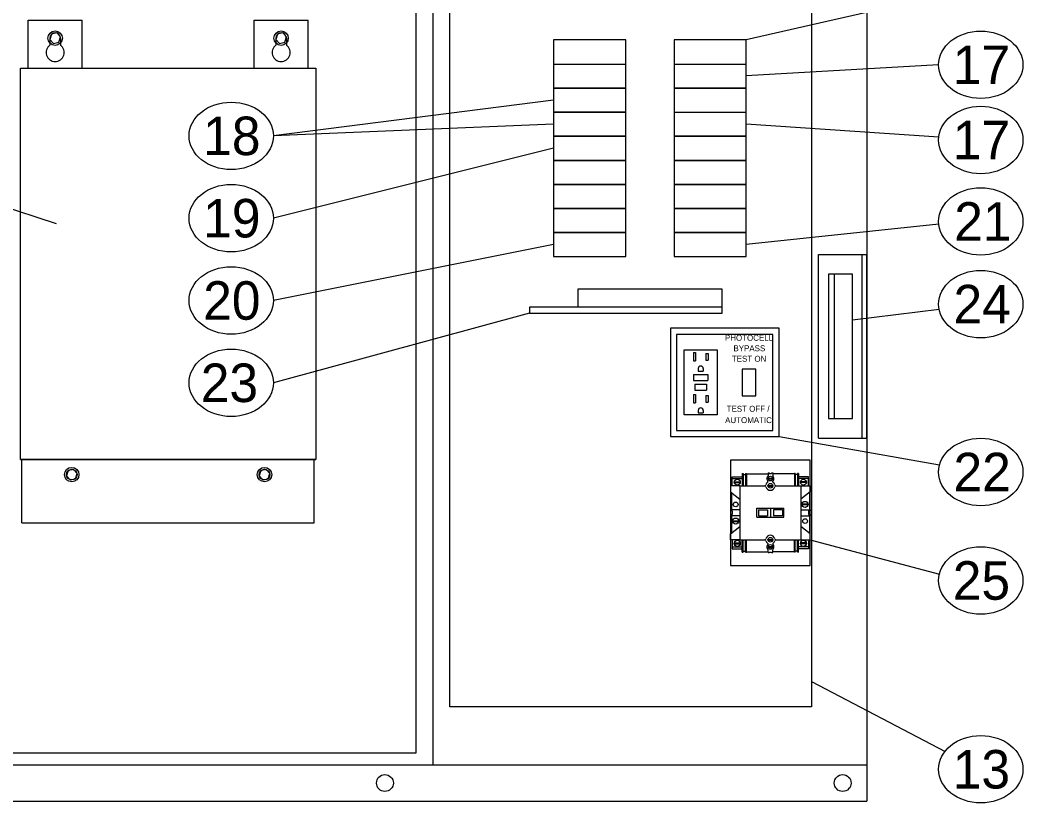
# Model space of a CAD drawing. Extents: x 99862 to 103680, y 99470 to 105076.
# Drawn here: x 102025.2 to 102441.5, y 104497.2 to 104822.4 of the extents above; entities that cross this region are included whole.
import ezdxf

# ---------------------------------------------------------------- set-up
doc = ezdxf.new("R2010")
doc.units = 0
for name, color, linetype in [('Level 1', 7, 'Continuous'), ('Level 15', 7, 'Continuous'), ('Level 20', 7, 'Continuous'), ('Level 40', 7, 'Continuous')]:
    doc.layers.add(name, color=color, linetype=linetype)

msp = doc.modelspace()

# ---------------------------------------------------------------- linework, layer by layer
at = {"layer": 'Level 1'}
for p, q in [((102203.66, 104537.04), (102203.66, 104897.04)), ((102353.66, 104897.04), (102353.66, 104537.04)), ((102189.66, 104518.01), (102189.66, 104892.87)), ((102028.51, 104802.34), (102028.51, 104822.34)), ((102028.51, 104822.34), (102051.01, 104822.34)), ((102051.01, 104802.34), (102051.01, 104822.34)), ((102122.31, 104802.34), (102122.31, 104822.34)), ((102122.31, 104822.34), (102144.81, 104822.34)), ((102144.81, 104802.34), (102144.81, 104822.34)), ((102037.56, 104814.84), (102037.56, 104811.93)), ((102041.96, 104814.84), (102041.96, 104811.93)), ((102131.36, 104814.84), (102131.36, 104811.93)), ((102135.76, 104814.84), (102135.76, 104811.93)), ((102246.66, 104804.08), (102276.66, 104804.08)), ((102296.66, 104804.08), (102326.66, 104804.08)), ((102296.66, 104784.08), (102326.66, 104784.08)), ((102356.66, 104648.69), (102356.66, 104724.94)), ((102356.66, 104724.94), (102376.66, 104724.94)), ((102374.79, 104648.69), (102374.79, 104724.94)), ((102376.66, 104648.69), (102376.66, 104724.94)), ((102300.84, 104658.31), (102300.84, 104685.31)), ((102300.84, 104685.31), (102314.62, 104685.31)), ((102304.68, 104684.2), (102305.54, 104684.2)), ((102304.68, 104684.2), (102304.68, 104680.74)), ((102305.54, 104684.2), (102305.54, 104680.74)), ((102309.9, 104683.84), (102309.9, 104681.03)), ((102309.9, 104683.84), (102310.77, 104683.84)), ((102310.77, 104683.84), (102310.77, 104681.03)), ((102314.62, 104685.31), (102314.62, 104658.31)), ((102304.68, 104680.74), (102305.54, 104680.74)), ((102306.65, 104677.6), (102306.65, 104676.58)), ((102308.78, 104677.6), (102308.78, 104676.58)), ((102309.9, 104681.03), (102310.77, 104681.03)), ((102304.73, 104675.08), (102310.73, 104675.08)), ((102304.73, 104675.08), (102304.73, 104672.62)), ((102306.65, 104676.58), (102308.78, 104676.58)), ((102310.73, 104675.08), (102310.73, 104672.62)), ((102304.73, 104672.62), (102310.73, 104672.62)), ((102305.23, 104671.06), (102305.23, 104668.66)), ((102305.23, 104671.06), (102310.19, 104671.06)), ((102310.19, 104671.06), (102310.19, 104668.66)), ((102304.68, 104666.82), (102305.54, 104666.82)), ((102304.68, 104666.82), (102304.68, 104663.37)), ((102305.23, 104668.66), (102310.19, 104668.66)), ((102305.54, 104666.82), (102305.54, 104663.37)), ((102309.9, 104666.47), (102309.9, 104663.66)), ((102309.9, 104666.47), (102310.77, 104666.47)), ((102310.77, 104666.47), (102310.77, 104663.66)), ((102304.68, 104663.37), (102305.54, 104663.37)), ((102309.9, 104663.66), (102310.77, 104663.66)), ((102314.62, 104658.31), (102300.84, 104658.31)), ((102306.65, 104660.22), (102306.65, 104659.21)), ((102306.65, 104659.21), (102308.78, 104659.21)), ((102308.78, 104660.22), (102308.78, 104659.21)), ((102356.66, 104648.69), (102376.66, 104648.69)), ((102025.41, 104639.87), (102147.91, 104639.87)), ((102025.98, 104613.54), (102025.98, 104639.87)), ((102147.34, 104613.54), (102147.34, 104639.87)), ((102320.84, 104628.91), (102320.84, 104632.65)), ((102320.84, 104632.65), (102324.96, 104632.65)), ((102320.84, 104631.9), (102324.96, 104631.9)), ((102324.96, 104634.02), (102324.96, 104628.91)), ((102324.96, 104634.02), (102325.33, 104634.02)), ((102325.33, 104634.02), (102325.33, 104628.91)), ((102325.33, 104633.65), (102326.33, 104633.65)), ((102326.33, 104634.02), (102326.33, 104628.91)), ((102326.33, 104634.02), (102326.7, 104634.02)), ((102326.7, 104634.02), (102326.7, 104628.91)), ((102326.7, 104633.9), (102335.68, 104633.9)), ((102335.66, 104632.06), (102337.63, 104632.06)), ((102335.66, 104631.74), (102337.63, 104631.74)), ((102335.68, 104634.27), (102335.68, 104633.04)), ((102335.68, 104634.27), (102336.18, 104634.27)), ((102336.18, 104634.27), (102336.18, 104634.02)), ((102336.18, 104634.02), (102337.12, 104634.02)), ((102337.12, 104634.27), (102337.62, 104634.27)), ((102337.12, 104634.27), (102337.12, 104634.02)), ((102337.62, 104634.27), (102337.62, 104633.04)), ((102346.6, 104633.9), (102337.62, 104633.9)), ((102346.6, 104634.02), (102346.6, 104628.91)), ((102346.97, 104634.02), (102346.6, 104634.02)), ((102346.97, 104634.02), (102346.97, 104628.91)), ((102347.97, 104633.65), (102346.97, 104633.65)), ((102347.97, 104634.02), (102347.97, 104628.91)), ((102348.34, 104634.02), (102347.97, 104634.02)), ((102348.34, 104634.02), (102348.34, 104628.91)), ((102352.45, 104632.65), (102348.34, 104632.65)), ((102352.45, 104631.9), (102348.34, 104631.9)), ((102352.45, 104628.91), (102352.45, 104632.65)), ((102324.02, 104628.91), (102320.1, 104628.91)), ((102320.1, 104628.91), (102320.1, 104626.42)), ((102321.66, 104630.57), (102324.14, 104630.57)), ((102321.66, 104630.25), (102324.14, 104630.25)), ((102324.02, 104628.91), (102324.02, 104606.49)), ((102324.02, 104628.91), (102334.33, 104628.91)), ((102335.59, 104630.46), (102335.59, 104630.85)), ((102335.66, 104629.07), (102337.63, 104629.07)), ((102335.66, 104628.75), (102337.63, 104628.75)), ((102337.7, 104630.46), (102337.7, 104630.85)), ((102338.96, 104628.91), (102349.27, 104628.91)), ((102351.63, 104630.57), (102349.16, 104630.57)), ((102351.63, 104630.25), (102349.16, 104630.25)), ((102349.27, 104628.91), (102349.27, 104606.49)), ((102349.27, 104628.91), (102353.2, 104628.91)), ((102353.2, 104628.91), (102353.2, 104626.42)), ((102320.1, 104626.42), (102324.02, 104623.37)), ((102320.47, 104626.13), (102320.47, 104618.95)), ((102353.2, 104626.42), (102349.27, 104623.37)), ((102352.82, 104626.13), (102352.82, 104618.95)), ((102331.04, 104615.83), (102331.04, 104619.57)), ((102331.04, 104619.57), (102342.25, 104619.57)), ((102336.65, 104619.26), (102336.65, 104616.15)), ((102342.25, 104615.83), (102342.25, 104619.57)), ((102352.28, 104621.32), (102349.81, 104621.32)), ((102352.28, 104621), (102349.81, 104621)), ((102320.1, 104618.95), (102320.1, 104618.45)), ((102324.02, 104618.95), (102320.1, 104618.95)), ((102320.84, 104618.45), (102320.1, 104618.45)), ((102320.1, 104616.96), (102320.1, 104616.46)), ((102320.84, 104616.96), (102320.1, 104616.96)), ((102324.02, 104616.46), (102320.1, 104616.46)), ((102320.47, 104616.46), (102320.47, 104609.27)), ((102320.84, 104618.45), (102320.84, 104616.96)), ((102331.04, 104615.83), (102342.25, 104615.83)), ((102331.66, 104618.95), (102335.4, 104618.95)), ((102331.66, 104618.95), (102331.66, 104616.46)), ((102331.66, 104616.46), (102335.4, 104616.46)), ((102335.4, 104618.95), (102335.4, 104616.46)), ((102341.63, 104618.95), (102337.89, 104618.95)), ((102337.89, 104618.95), (102337.89, 104616.46)), ((102341.63, 104616.46), (102337.89, 104616.46)), ((102341.63, 104618.95), (102341.63, 104616.46)), ((102349.27, 104618.95), (102353.2, 104618.95)), ((102349.27, 104616.46), (102353.2, 104616.46)), ((102352.45, 104618.45), (102352.45, 104616.96)), ((102352.45, 104618.45), (102353.2, 104618.45)), ((102352.45, 104616.96), (102353.2, 104616.96)), ((102352.82, 104616.46), (102352.82, 104609.27)), ((102353.2, 104618.95), (102353.2, 104618.45)), ((102353.2, 104616.96), (102353.2, 104616.46)), ((102025.98, 104613.54), (102147.34, 104613.54)), ((102320.1, 104608.98), (102324.02, 104612.04)), ((102321.01, 104614.41), (102323.48, 104614.41)), ((102321.01, 104614.09), (102323.48, 104614.09)), ((102353.2, 104608.98), (102349.27, 104612.04)), ((102320.1, 104606.49), (102320.1, 104608.98)), ((102353.2, 104606.49), (102353.2, 104608.98)), ((102324.02, 104606.49), (102320.1, 104606.49)), ((102320.84, 104606.49), (102320.84, 104602.76)), ((102320.84, 104603.5), (102324.96, 104603.5)), ((102320.84, 104602.76), (102324.96, 104602.76)), ((102321.66, 104605.16), (102324.14, 104605.16)), ((102321.66, 104604.84), (102324.14, 104604.84)), ((102324.02, 104606.49), (102334.33, 104606.49)), ((102324.96, 104601.39), (102324.96, 104606.49)), ((102325.33, 104601.39), (102325.33, 104606.49)), ((102326.33, 104601.39), (102326.33, 104606.49)), ((102326.7, 104601.39), (102326.7, 104606.49)), ((102335.59, 104604.95), (102335.59, 104604.56)), ((102335.66, 104606.65), (102337.63, 104606.65)), ((102335.66, 104606.33), (102337.63, 104606.33)), ((102335.66, 104603.66), (102337.63, 104603.66)), ((102335.66, 104603.34), (102337.63, 104603.34)), ((102337.7, 104604.95), (102337.7, 104604.56)), ((102338.96, 104606.49), (102349.27, 104606.49)), ((102346.6, 104601.39), (102346.6, 104606.49)), ((102346.97, 104601.39), (102346.97, 104606.49)), ((102347.97, 104601.39), (102347.97, 104606.49)), ((102348.34, 104601.39), (102348.34, 104606.49)), ((102352.45, 104603.5), (102348.34, 104603.5)), ((102352.45, 104602.76), (102348.34, 104602.76)), ((102351.63, 104605.16), (102349.16, 104605.16)), ((102351.63, 104604.84), (102349.16, 104604.84)), ((102349.27, 104606.49), (102353.2, 104606.49)), ((102352.45, 104606.49), (102352.45, 104602.76)), ((102324.96, 104601.39), (102325.33, 104601.39)), ((102325.33, 104601.76), (102326.33, 104601.76)), ((102326.33, 104601.39), (102326.7, 104601.39)), ((102326.7, 104601.51), (102335.68, 104601.51)), ((102335.68, 104601.14), (102335.68, 104602.36)), ((102335.68, 104601.14), (102336.18, 104601.14)), ((102336.18, 104601.39), (102337.12, 104601.39)), ((102336.18, 104601.14), (102336.18, 104601.38)), ((102337.12, 104601.14), (102337.12, 104601.39)), ((102337.12, 104601.14), (102337.62, 104601.14)), ((102337.62, 104601.14), (102337.62, 104602.36)), ((102346.6, 104601.51), (102337.62, 104601.51)), ((102346.97, 104601.39), (102346.6, 104601.39)), ((102347.97, 104601.76), (102346.97, 104601.76)), ((102348.34, 104601.39), (102347.97, 104601.39)), ((102353.66, 104537.04), (102203.66, 104537.04))]:
    msp.add_line(p, q, dxfattribs=at)
for points in [[(102246.66, 104794.08), (102276.66, 104794.08), (102276.66, 104814.08), (102246.66, 104814.08)], [(102296.66, 104794.08), (102326.66, 104794.08), (102326.66, 104814.08), (102296.66, 104814.08)], [(102025.41, 104802.34), (102147.91, 104802.34), (102147.91, 104639.87), (102025.41, 104639.87)], [(102246.66, 104784.08), (102276.66, 104784.08), (102276.66, 104794.08), (102246.66, 104794.08)], [(102296.66, 104774.08), (102326.66, 104774.08), (102326.66, 104794.08), (102296.66, 104794.08)], [(102246.66, 104774.08), (102276.66, 104774.08), (102276.66, 104784.08), (102246.66, 104784.08)], [(102246.66, 104764.08), (102276.66, 104764.08), (102276.66, 104774.08), (102246.66, 104774.08)], [(102296.66, 104764.08), (102326.66, 104764.08), (102326.66, 104774.08), (102296.66, 104774.08)], [(102246.66, 104754.08), (102276.66, 104754.08), (102276.66, 104764.08), (102246.66, 104764.08)], [(102296.66, 104754.08), (102326.66, 104754.08), (102326.66, 104764.08), (102296.66, 104764.08)], [(102246.66, 104744.08), (102276.66, 104744.08), (102276.66, 104754.08), (102246.66, 104754.08)], [(102296.66, 104744.08), (102326.66, 104744.08), (102326.66, 104754.08), (102296.66, 104754.08)], [(102246.66, 104734.08), (102276.66, 104734.08), (102276.66, 104744.08), (102246.66, 104744.08)], [(102296.66, 104734.08), (102326.66, 104734.08), (102326.66, 104744.08), (102296.66, 104744.08)], [(102246.66, 104724.08), (102276.66, 104724.08), (102276.66, 104734.08), (102246.66, 104734.08)], [(102296.66, 104724.08), (102326.66, 104724.08), (102326.66, 104734.08), (102296.66, 104734.08)], [(102360.72, 104716.81), (102360.72, 104656.81), (102370.72, 104656.81), (102370.72, 104716.81)], [(102363.22, 104656.81), (102363.22, 104716.81), (102360.72, 104716.81), (102360.72, 104656.81)], [(102316.66, 104703.06), (102236.66, 104703.06), (102236.66, 104700.56), (102316.66, 104700.56)], [(102295.23, 104649.31), (102340.23, 104649.31), (102340.23, 104694.31), (102295.23, 104694.31)], [(102297.73, 104651.81), (102337.73, 104651.81), (102337.73, 104691.81), (102297.73, 104691.81)], [(102324.89, 104677.34), (102324.89, 104666.27), (102330.56, 104666.27), (102330.56, 104677.34)], [(102353.2, 104639.6), (102320.1, 104639.6), (102320.1, 104595.8), (102353.2, 104595.8)]]:
    msp.add_lwpolyline(points, close=True, dxfattribs=at)
msp.add_lwpolyline([(102256.66, 104700.56), (102316.66, 104700.56), (102316.66, 104710.56), (102256.66, 104710.56), (102256.66, 104703.06)], dxfattribs=at)
for centre, radius in [((102046.66, 104633.54), 2.2), ((102126.66, 104633.54), 2.2), ((102322.9, 104630.41), 1.25), ((102336.65, 104631.9), 0.997), ((102350.39, 104630.41), 1.25), ((102336.65, 104628.91), 0.997), ((102322.25, 104621.16), 0.997), ((102351.05, 104621.16), 1.25), ((102322.25, 104614.25), 1.25), ((102351.05, 104614.25), 0.997), ((102336.65, 104606.49), 0.997), ((102322.9, 104605), 1.25), ((102336.65, 104603.5), 0.997), ((102350.39, 104605), 1.25)]:
    msp.add_circle(centre, radius, dxfattribs=at)
for centre, radius, start, end in [((102039.76, 104814.84), 2.2, 0, 180), ((102133.56, 104814.84), 2.2, 0, 180), ((102039.76, 104808.89), 3.75, 125.9208, 54.0792), ((102133.56, 104808.89), 3.75, 125.9208, 54.0792), ((102307.72, 104677.6), 1.06, 360, 180), ((102307.72, 104660.22), 1.06, 360, 180), ((102336.65, 104631.9), 1.49, 130.4046, 225), ((102336.65, 104631.9), 1.49, 315, 49.5954), ((102334.33, 104629.41), 0.498, 270, 347.8468), ((102334.33, 104628.42), 0.498, 12.1532, 90), ((102336.65, 104628.91), 1.87, 124.4499, 167.8469), ((102336.65, 104628.91), 1.87, 192.1531, 347.8468), ((102336.65, 104628.91), 1.87, 12.1532, 55.5501), ((102338.96, 104629.41), 0.498, 192.1532, 270), ((102338.96, 104628.42), 0.498, 90, 167.8468), ((102334.33, 104606.99), 0.498, 270, 347.8468), ((102336.65, 104606.49), 1.87, 12.1532, 167.8469), ((102338.96, 104606.99), 0.498, 192.1532, 270), ((102334.33, 104605.99), 0.498, 12.1532, 90), ((102336.65, 104606.49), 1.87, 192.1531, 235.5501), ((102336.65, 104603.5), 1.49, 135, 229.5954), ((102336.65, 104603.5), 1.49, 310.4046, 45), ((102336.65, 104606.49), 1.87, 304.4499, 347.8468), ((102338.96, 104605.99), 0.498, 90, 167.8468)]:
    msp.add_arc(centre, radius, start, end, dxfattribs=at)
at = {"layer": 'Level 15'}
for p, q in [((102407.16, 104832.53), (102326.66, 104814.08)), ((102406.48, 104803.77), (102326.66, 104799.14)), ((102246.66, 104789.08), (102130.34, 104774.25)), ((102246.66, 104779.08), (102130.34, 104774.25)), ((102406.54, 104773.72), (102326.66, 104779.14)), ((102246.66, 104769.08), (102130.34, 104740.06)), ((102040.35, 104737.78), (101955.68, 104765.11)), ((102406.54, 104737.52), (102326.66, 104729.08)), ((102246.66, 104729.08), (102130.34, 104705.87)), ((102236.66, 104700.56), (102130.34, 104671.68)), ((102370.72, 104697.9), (102406.68, 104702.26)), ((102340.23, 104649.31), (102406.88, 104637.63)), ((102353.2, 104606.49), (102406.8, 104592.26)), ((102353.66, 104547.57), (102409.13, 104518.57))]:
    msp.add_line(p, q, dxfattribs=at)
for centre in [(102176.66, 104505.44), (102366.66, 104505.44)]:
    msp.add_circle(centre, 3.5, dxfattribs=at)
at = {"layer": 'Level 20'}
for centre in [(102423.98, 104803.77), (102112.84, 104774.25), (102423.98, 104772.53), (102112.84, 104740.06), (102423.98, 104738.7), (102112.84, 104705.87), (102423.98, 104704.35), (102112.84, 104671.68), (102423.98, 104634.63), (102423.98, 104589.57), (102423.98, 104511.16)]:
    msp.add_ellipse(centre, major_axis=(-17.5, 0), ratio=0.8, dxfattribs=at)
at = {"layer": 'Level 40'}
for p, q in [((102196.66, 104512.94), (102196.66, 104902.94)), ((102376.66, 104902.94), (102376.66, 104497.94)), ((101983.66, 104518.01), (102189.66, 104518.01)), ((101976.66, 104512.94), (102376.66, 104512.94)), ((101976.66, 104497.94), (102376.66, 104497.94))]:
    msp.add_line(p, q, dxfattribs=at)
for points in [[(102041.32, 104813.16), (102041.99, 104815.34), (102040.44, 104817.02), (102038.21, 104816.52), (102037.53, 104814.33), (102039.08, 104812.65)], [(102135.12, 104813.16), (102135.79, 104815.34), (102134.24, 104817.02), (102132.01, 104816.52), (102131.33, 104814.33), (102132.88, 104812.65)], [(102048.22, 104631.86), (102048.89, 104634.04), (102047.34, 104635.72), (102045.11, 104635.22), (102044.43, 104633.03), (102045.98, 104631.35)], [(102128.22, 104631.86), (102128.89, 104634.04), (102127.34, 104635.72), (102125.11, 104635.22), (102124.43, 104633.03), (102125.98, 104631.35)]]:
    msp.add_lwpolyline(points, close=True, dxfattribs=at)
for centre in [(102039.76, 104814.84), (102133.56, 104814.84), (102046.66, 104633.54), (102126.66, 104633.54)]:
    msp.add_circle(centre, 2.99, dxfattribs=at)

# ---------------------------------------------------------------- texts
at = {"layer": 'Level 20'}
for s, p in [('17', (102412.35, 104795.77)), ('18', (102101.21, 104766.25)), ('17', (102412.35, 104764.53)), ('19', (102101.21, 104732.06)), ('21', (102412.96, 104730.7)), ('20', (102101.21, 104697.87)), ('24', (102412.65, 104696.35)), ('23', (102100.21, 104663.68)), ('22', (102412.65, 104626.63)), ('25', (102412.35, 104581.57)), ('13', (102412.35, 104503.16))]:
    msp.add_text(s, height=16, dxfattribs=at).set_placement(p)
at = {"layer": 'Level 40'}
for s, p in [('PHOTOCELL', (102317.79, 104689.14)), ('BYPASS', (102321.32, 104684.79)), ('TEST ON', (102320.67, 104680.44)), ('TEST OFF /', (102318.51, 104659.66)), ('AUTOMATIC', (102317.86, 104654.94))]:
    msp.add_text(s, height=2.467, rotation=360, dxfattribs=at).set_placement(p)

doc.saveas('drawing.dxf')
